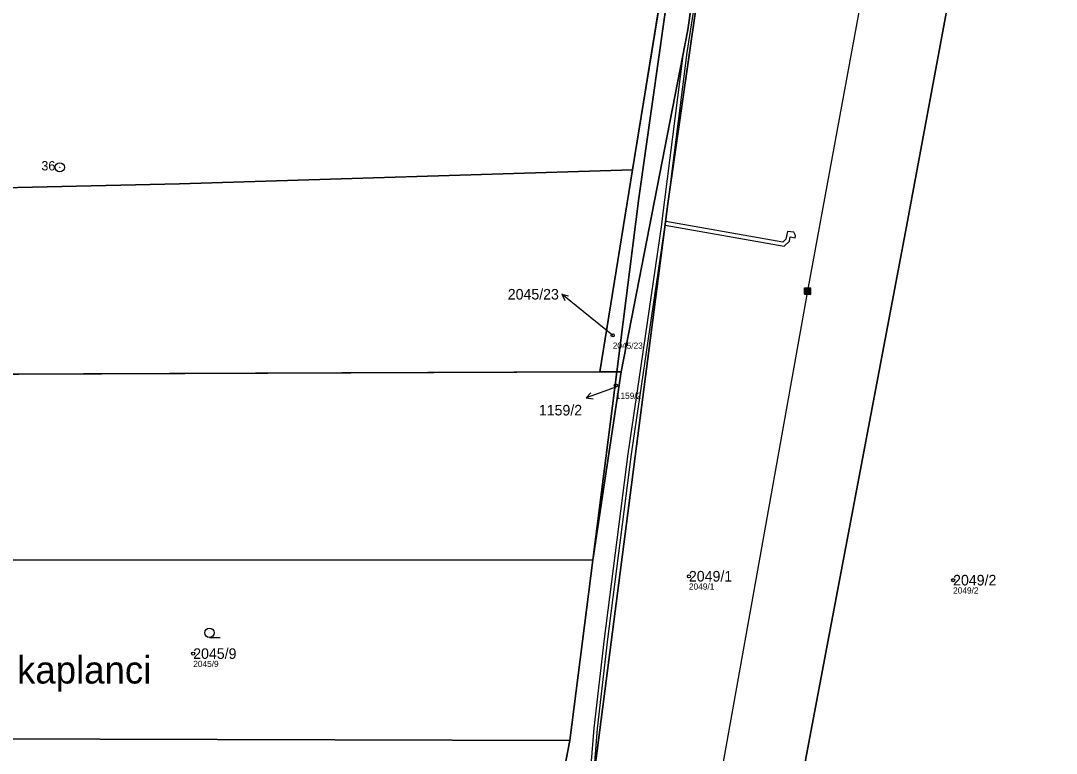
# Model space of a CAD drawing. Extents: x -762274 to -759271, y -1061928 to -1059060.
# Drawn here: x -760119.6 to -759953.1, y -1059986.3 to -1059868.4 of the extents above; entities that cross this region are included whole.
import ezdxf

# ---------------------------------------------------------------- set-up
doc = ezdxf.new("R2010")
doc.units = 0
for name, color, linetype in [('Definiční body', 7, 'Continuous'), ('Hranice parcel', 7, 'Continuous'), ('Parcelní čísla', 7, 'Continuous'), ('Polygon parcely', 7, 'Continuous'), ('Pop  PČ popisy', 7, 'Continuous'), ('Poz předměty', 7, 'Continuous'), ('Věcná břemena k části', 7, 'Continuous'), ('Značky bodu BP', 7, 'Continuous'), ('Značky kultur', 7, 'Continuous')]:
    doc.layers.add(name, color=color, linetype=linetype)

msp = doc.modelspace()

# ---------------------------------------------------------------- linework, layer by layer
at = {"layer": 'Definiční body'}
for centre in [(-760024.39, -1059919.04), (-760023.9, -1059927.1), (-760012.14, -1059957.8), (-759969.66, -1059958.43), (-760091.85, -1059970.25)]:
    msp.add_circle(centre, 0.25, dxfattribs=at)
at = {"layer": 'Hranice parcel'}
for p, q in [((-760021.2, -1059892.43), (-760015.88, -1059859.54)), ((-760026.46, -1059924.92), (-760021.2, -1059892.43)), ((-760026.46, -1059924.92), (-760253.48, -1059925.84)), ((-760027.59, -1059955.21), (-760023.74, -1059924.91)), ((-760027.59, -1059955.21), (-760023.04, -1059924.91)), ((-760023.74, -1059924.91), (-760026.46, -1059924.92)), ((-760023.04, -1059924.91), (-760023.74, -1059924.91)), ((-760144.86, -1059955.17), (-760027.59, -1059955.21)), ((-760031.29, -1059984.24), (-760027.59, -1059955.21)), ((-760144.68, -1059983.88), (-760031.29, -1059984.24)), ((-760031.29, -1059984.24), (-760032.52, -1059990.62))]:
    msp.add_line(p, q, dxfattribs=at)
for points in [[(-760027.51, -1059990.4), (-760015.46, -1059897.47), (-760001.01, -1059796.76)], [(-760001.77, -1059796.64), (-760004.46, -1059813.85), (-760012.29, -1059869.87), (-760023.04, -1059924.91)], [(-760014.8, -1060091), (-760008.77, -1060066.75), (-759995.99, -1060001.03), (-759989.95, -1059969.21), (-759977.18, -1059901.54), (-759957.93, -1059797.95)], [(-760014.89, -1059859.5), (-760020.17, -1059896.95), (-760023.74, -1059924.91)], [(-760248.82, -1059897.39), (-760241.04, -1059896.41), (-760194.86, -1059896.23), (-760139, -1059895.68), (-760094.08, -1059894.69), (-760021.2, -1059892.43)]]:
    msp.add_lwpolyline(points, dxfattribs=at)
at = {"layer": 'Polygon parcely'}
for points in [[(-759957.93, -1059797.95), (-759970.48, -1059792.55), (-759998.02, -1059783.24), (-760001.01, -1059796.76), (-760015.46, -1059897.47), (-760027.51, -1059990.4), (-760032.76, -1060019.15), (-760038.3, -1060033.39), (-760046.97, -1060048.1), (-760051.87, -1060060.98), (-760057.38, -1060080.77), (-760014.8, -1060091), (-760008.77, -1060066.75), (-759995.99, -1060001.03), (-759989.95, -1059969.21), (-759977.18, -1059901.54)], [(-760020.17, -1059896.95), (-760023.74, -1059924.91), (-760023.04, -1059924.91), (-760012.29, -1059869.87), (-760004.46, -1059813.85), (-760001.77, -1059796.64), (-760005.93, -1059795.98), (-760014.89, -1059859.5)], [(-760031.29, -1059984.24), (-760032.52, -1059990.62), (-760038.02, -1060019.22), (-760039.64, -1060031.93), (-760049.68, -1060049.27), (-760051.87, -1060060.98), (-760046.97, -1060048.1), (-760038.3, -1060033.39), (-760032.76, -1060019.15), (-760027.51, -1059990.4), (-760015.46, -1059897.47), (-760001.01, -1059796.76), (-760001.77, -1059796.64), (-760004.46, -1059813.85), (-760012.29, -1059869.87), (-760023.04, -1059924.91), (-760027.59, -1059955.21)], [(-759913.18, -1059816.61), (-759918.25, -1059814.68), (-759952.81, -1059800.15), (-759957.93, -1059797.95), (-759977.18, -1059901.54), (-759989.95, -1059969.21), (-759995.99, -1060001.03), (-760008.77, -1060066.75), (-760014.8, -1060091), (-760013.72, -1060091.26), (-759983.22, -1060098.46), (-759966.43, -1060102.05), (-759947.9, -1059994.09), (-759932.29, -1059907.12)], [(-760194.86, -1059896.23), (-760139, -1059895.68), (-760094.08, -1059894.69), (-760021.2, -1059892.43), (-760015.88, -1059859.54), (-760133.38, -1059864), (-760200.3, -1059865.54), (-760212.79, -1059865.82), (-760242.13, -1059866.5), (-760246.39, -1059882.54), (-760248.82, -1059897.39), (-760241.04, -1059896.41)], [(-760026.46, -1059924.92), (-760023.74, -1059924.91), (-760020.17, -1059896.95), (-760014.89, -1059859.5), (-760015.88, -1059859.54), (-760021.2, -1059892.43)], [(-760026.46, -1059924.92), (-760021.2, -1059892.43), (-760094.08, -1059894.69), (-760139, -1059895.68), (-760194.86, -1059896.23), (-760241.04, -1059896.41), (-760248.82, -1059897.39), (-760253.48, -1059925.84)], [(-760027.59, -1059955.21), (-760023.74, -1059924.91), (-760026.46, -1059924.92), (-760253.48, -1059925.84), (-760255.81, -1059940.12), (-760256.14, -1059942.1), (-760241.49, -1059948.59), (-760235.12, -1059957.46), (-760204.15, -1059955.35), (-760180.55, -1059955.64), (-760144.86, -1059955.17)], [(-760027.59, -1059955.21), (-760023.04, -1059924.91), (-760023.74, -1059924.91)], [(-760031.29, -1059984.24), (-760027.59, -1059955.21), (-760144.86, -1059955.17), (-760144.85, -1059957.17), (-760144.68, -1059983.88)]]:
    msp.add_lwpolyline(points, close=True, dxfattribs=at)
msp.add_lwpolyline([(-760147.84, -1059992.72), (-760105.64, -1059990.87), (-760076.41, -1059990.86), (-760075.16, -1059990.86), (-760070.36, -1059990.72), (-760068.77, -1059990.67), (-760032.52, -1059990.62), (-760031.29, -1059984.24), (-760144.68, -1059983.88)], dxfattribs=at)
at = {"layer": 'Pop  PČ popisy'}
for p, q in [((-760030.25, -1059914.31), (-760032.58, -1059912.42)), ((-760032.58, -1059912.42), (-760031.49, -1059912.66)), ((-760032.58, -1059912.42), (-760032.12, -1059913.44)), ((-760024.39, -1059919.04), (-760030.25, -1059914.31)), ((-760023.8, -1059927.35), (-760025.84, -1059928.08)), ((-760025.84, -1059928.08), (-760028.66, -1059929.11)), ((-760028.66, -1059929.11), (-760027.89, -1059928.29)), ((-760028.66, -1059929.11), (-760027.55, -1059929.23))]:
    msp.add_line(p, q, dxfattribs=at)
at = {"layer": 'Poz předměty'}
for p, q in [((-759944.94, -1059649.68), (-759993.06, -1059911.9)), ((-759993.06, -1059911.9), (-760049.01, -1060224.35)), ((-759993.56, -1059911.4), (-759992.56, -1059911.4)), ((-759993.56, -1059912.4), (-759993.56, -1059911.4)), ((-759993.56, -1059911.6), (-759992.56, -1059911.6)), ((-759993.56, -1059911.8), (-759992.56, -1059911.8)), ((-759993.56, -1059912), (-759992.56, -1059912)), ((-759993.56, -1059912.2), (-759992.56, -1059912.2)), ((-759993.56, -1059912.4), (-759992.56, -1059912.4)), ((-759993.36, -1059912.4), (-759993.36, -1059911.4)), ((-759993.16, -1059912.4), (-759993.16, -1059911.4)), ((-759992.96, -1059912.4), (-759992.96, -1059911.4)), ((-759992.76, -1059912.4), (-759992.76, -1059911.4)), ((-759992.56, -1059912.4), (-759992.56, -1059911.4))]:
    msp.add_line(p, q, dxfattribs=at)
at = {"layer": 'Věcná břemena k části'}
for points in [[(-760027.43, -1059989.82), (-760026.83, -1059982.29), (-760025.16, -1059967.94), (-760021.37, -1059938.17), (-760015.96, -1059901.31), (-759996.83, -1059904.7), (-759995.99, -1059903.89), (-759995.86, -1059903.2), (-759995.04, -1059903.34), (-759994.98, -1059903), (-759995.29, -1059902.42), (-759996.3, -1059902.31), (-759996.55, -1059903.59), (-759997.03, -1059904.06), (-760015.88, -1059900.71), (-760012.42, -1059873.52), (-760009.55, -1059855.04)], [(-760010.75, -1059858.84), (-760012.29, -1059869.87), (-760013.1, -1059874), (-760016.47, -1059900.61), (-760016.56, -1059901.2), (-760020.18, -1059926.15), (-760021.97, -1059938.09), (-760025.76, -1059967.86), (-760027.43, -1059982.23), (-760028.17, -1059991.51)]]:
    msp.add_lwpolyline(points, dxfattribs=at)
at = {"layer": 'Značky bodu BP'}
for radius in [0.75, 0.03]:
    msp.add_circle((-760113.3, -1059892.01), radius, dxfattribs=at)
at = {"layer": 'Značky kultur'}
msp.add_line((-760089.24, -1059967.65), (-760087.49, -1059967.65), dxfattribs=at)
msp.add_circle((-760089.24, -1059966.9), 0.75, dxfattribs=at)

# ---------------------------------------------------------------- texts
at = {"layer": 'Definiční body'}
for s, p in [('2045/23', (-760024.39, -1059921.2)), ('1159/2', (-760023.9, -1059929.26)), ('2049/1', (-760012.14, -1059959.96)), ('2049/2', (-759969.66, -1059960.59)), ('2045/9', (-760091.85, -1059972.41))]:
    msp.add_text(s, height=1, dxfattribs=at).set_placement(p)
at = {"layer": 'Parcelní čísla'}
for s, p in [('2045/23', (-760041.27, -1059913.28)), ('1159/2', (-760036.27, -1059931.93)), ('2049/1', (-760012.14, -1059958.65)), ('2049/2', (-759969.66, -1059959.28)), ('2045/9', (-760091.85, -1059971.1))]:
    msp.add_text(s, height=1.7, dxfattribs=at).set_placement(p)
at = {"layer": 'Pop  PČ popisy'}
msp.add_text('Na kaplanci', height=4.4, dxfattribs=at).set_placement((-760129.33, -1059975.06))
at = {"layer": 'Značky bodu BP'}
msp.add_text('36', height=1.5, dxfattribs=at).set_placement((-760116.26, -1059892.51))

doc.saveas('drawing.dxf')
